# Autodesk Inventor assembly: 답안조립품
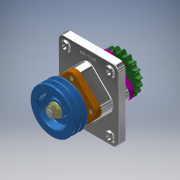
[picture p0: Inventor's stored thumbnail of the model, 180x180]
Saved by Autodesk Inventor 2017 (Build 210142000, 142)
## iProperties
Part Number: 답안조립품
Material: 일반
Document SubType Name: Assembly
Designer: MRC
Author: MRC
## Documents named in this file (16)
- C:\Users\MRC\Desktop\710707V1022\답안조립품.iam
- C:\Users\MRC\Desktop\710707V1022\본체.ipt
- C:\Users\MRC\Desktop\710707V1022\M16 너트.ipt
- C:\Users\MRC\Desktop\710707V1022\V-벨트풀리.ipt
- C:\Users\MRC\Desktop\710707V1022\멈춤나사 M4.ipt
- C:\Users\MRC\Desktop\710707V1022\베어링 6206.ipt
- C:\Users\MRC\Desktop\710707V1022\볼트 M6.ipt
- C:\Users\MRC\Desktop\710707V1022\부시.ipt
- C:\Users\MRC\Desktop\710707V1022\오일실 30x42x8.ipt
- C:\Users\MRC\Desktop\710707V1022\오일실 30x45x8.ipt
- C:\Users\MRC\Desktop\710707V1022\체인 스프로킷.ipt
- C:\Users\MRC\Desktop\710707V1022\축.ipt
- C:\Users\MRC\Desktop\710707V1022\커버A.ipt
- C:\Users\MRC\Desktop\710707V1022\커버B.ipt
- C:\Users\MRC\Desktop\710707V1022\키 6x6x18.ipt
- C:\Users\MRC\Desktop\710707V1022\키 6x6x20.ipt
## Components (3 placed, 2 different names)
1. M16 너트:1
2. V-벨트풀리:1
3. M16 너트:2
